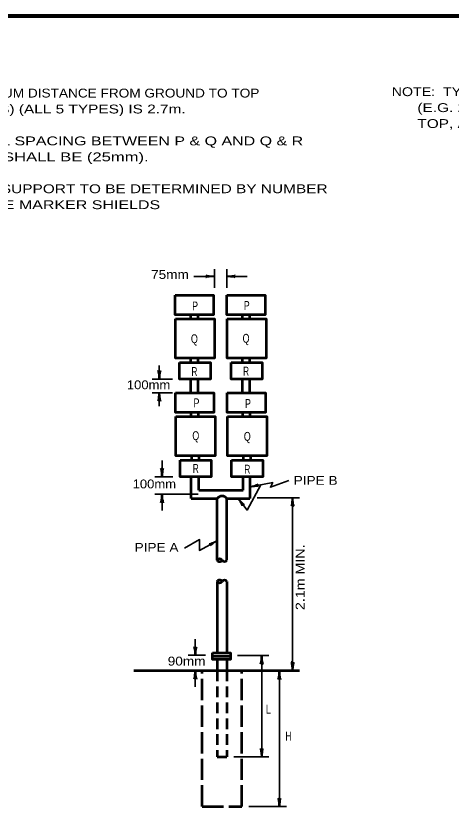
# Model space of a CAD drawing. Extents: x 11 to 867, y -284 to 260.
# Drawn here: x 281.9 to 429.3, y -14.9 to 254 of the extents above; entities that cross this region are included whole.
import ezdxf
from ezdxf.enums import TextEntityAlignment as Align

# ---------------------------------------------------------------- set-up
doc = ezdxf.new("R2010")
doc.units = 0
doc.header["$LTSCALE"] = 1.2
doc.linetypes.add('LONG_DASHED', pattern=[7.5, 6, -1.5])
doc.linetypes.add('MEDIUM_DASHED', pattern=[4.5, 3, -1.5])
doc.layers.add('1', color=7, linetype='Continuous', lineweight=53)

msp = doc.modelspace()

# ---------------------------------------------------------------- linework, layer by layer
at = {"layer": '1', "lineweight": 35}
for p, q in [((349.125, 161.883), (349.125, 168.204)), ((353.297, 161.883), (353.297, 168.204)), ((342.141, 165.805), (349.125, 165.805)), ((353.297, 165.805), (360.281, 165.805)), ((330.459, 131.031), (330.459, 135.62)), ((334.909, 131.031), (328.059, 131.031)), ((334.909, 126.419), (328.059, 126.419)), ((330.459, 121.829), (330.459, 126.419)), ((331.389, 97.999), (331.389, 103.499)), ((335.079, 97.967), (328.989, 97.967)), ((343.675, 92.038), (328.989, 92.038)), ((331.389, 86.538), (331.389, 92.038)), ((363.611, 90.861), (378.009, 90.861)), ((375.609, 32.333), (375.609, 90.861)), ((342.661, 37.489), (342.661, 43.001)), ((346.089, 37.489), (340.261, 37.489)), ((356.943, 37.381), (367.573, 37.381)), ((365.173, 37.381), (365.173, 3.099)), ((342.661, 26.821), (342.661, 32.333)), ((371.141, 32.206), (371.141, -13.726)), ((355.747, 3.099), (367.573, 3.099)), ((360.777, -13.726), (373.541, -13.726))]:
    msp.add_line(p, q, dxfattribs=at)
at = {"layer": '1'}
for p, q in [((341.177, 151.463), (341.177, 152.749)), ((343.685, 151.463), (343.685, 152.749)), ((358.679, 151.463), (358.679, 152.749)), ((361.187, 151.463), (361.187, 152.749)), ((341.177, 136.631), (341.177, 138.069)), ((343.685, 136.631), (343.685, 138.069)), ((358.679, 136.631), (358.679, 138.069)), ((361.187, 136.631), (361.187, 138.069)), ((341.177, 126.419), (341.177, 131.031)), ((343.685, 126.419), (343.685, 131.031)), ((358.679, 126.419), (358.679, 131.031)), ((361.187, 126.419), (361.187, 131.031)), ((341.177, 119.684), (341.177, 118.399)), ((343.685, 119.684), (343.685, 118.399)), ((358.679, 119.684), (358.679, 118.399)), ((361.187, 119.684), (361.187, 118.399)), ((341.413, 105.005), (341.413, 103.567)), ((343.857, 105.005), (343.857, 103.567)), ((358.915, 105.005), (358.915, 103.567)), ((361.359, 105.005), (361.359, 103.567)), ((341.275, 90.611), (341.275, 97.967)), ((343.879, 93.355), (343.879, 97.967)), ((358.849, 93.355), (358.849, 97.967)), ((361.211, 90.611), (361.211, 97.967)), ((343.879, 93.355), (358.849, 93.355)), ((341.275, 90.611), (350.073, 90.611)), ((350.073, 69.707), (350.073, 90.611)), ((353.347, 69.707), (353.347, 90.611)), ((353.347, 90.611), (361.185, 90.611)), ((350.075, 62.471), (350.075, 38.358)), ((353.347, 62.471), (353.347, 38.358)), ((348.489, 37.241), (354.543, 37.241)), ((350.075, 36.12), (350.075, 32.333)), ((353.347, 36.12), (353.347, 32.333)), ((321.829, 32.333), (378.009, 32.333))]:
    msp.add_line(p, q, dxfattribs=at)
at = {"layer": '1', "linetype": 'LONG_DASHED'}
msp.add_line((345.013, -13.726), (345.013, 32.333), dxfattribs=at)
at = {"layer": '1', "linetype": 'MEDIUM_DASHED'}
for p, q in [((350.075, 32.333), (350.075, 3.099)), ((353.347, 32.333), (353.347, 3.099)), ((350.075, 3.099), (353.347, 3.099))]:
    msp.add_line(p, q, dxfattribs=at)
at = {"layer": '1', "lineweight": 158}
msp.add_lwpolyline([(860.008, 254), (68.308, 253.9), (68.408, -272.101)], dxfattribs=at)
at = {"layer": '1'}
for points in [[(335.795, 159.483), (348.807, 159.483), (348.807, 152.749), (335.795, 152.749)], [(353.297, 159.483), (366.309, 159.483), (366.309, 152.749), (353.297, 152.749)], [(335.949, 151.463), (349.187, 151.463), (349.187, 138.069), (335.949, 138.069)], [(353.451, 151.463), (366.689, 151.463), (366.689, 138.069), (353.451, 138.069)], [(337.309, 136.631), (347.825, 136.631), (347.825, 131.031), (337.309, 131.031)], [(354.811, 136.631), (365.327, 136.631), (365.327, 131.031), (354.811, 131.031)], [(335.965, 126.419), (348.977, 126.419), (348.977, 119.684), (335.965, 119.684)], [(353.467, 126.419), (366.479, 126.419), (366.479, 119.684), (353.467, 119.684)], [(336.119, 118.399), (349.357, 118.399), (349.357, 105.005), (336.119, 105.005)], [(353.621, 118.399), (366.859, 118.399), (366.859, 105.005), (353.621, 105.005)], [(337.479, 103.567), (347.995, 103.567), (347.995, 97.967), (337.479, 97.967)], [(354.981, 103.567), (365.497, 103.567), (365.497, 97.967), (354.981, 97.967)], [(348.489, 38.358), (354.543, 38.358), (354.543, 36.12), (348.489, 36.12)]]:
    msp.add_lwpolyline(points, close=True, dxfattribs=at)
at = {"layer": '1', "lineweight": 35}
for points in [[(364.831, 95.209), (360.199, 86.669), (357.193, 90.611)], [(361.211, 94.532), (368.907, 95.969), (368.121, 94.397), (374.407, 96.689)], [(350.073, 76.264), (344.043, 73.031), (344.113, 76.654), (338.957, 73.727)]]:
    msp.add_lwpolyline(points, dxfattribs=at)
at = {"layer": '1', "linetype": 'LONG_DASHED'}
msp.add_lwpolyline([(345.013, -13.726), (358.377, -13.726), (358.377, 32.333)], dxfattribs=at)
at = {"layer": '1'}
for centre, radius, start, end in [((351.71, 89.228), 2.143, 40.17606, 139.82394), ((350.893, 69.15), 0.989, 34.21419, 145.78581), ((350.893, 70.145), 0.928, 208.21086, 331.78914), ((352.529, 70.286), 1.003, 215.33373, 324.66627), ((350.893, 62.032), 0.928, 28.21086, 151.78914), ((350.893, 63.027), 0.989, 214.21419, 325.78581), ((352.529, 61.891), 1.003, 35.33373, 144.66627)]:
    msp.add_arc(centre, radius, start, end, dxfattribs=at)
at = {"layer": '1', "lineweight": 40}
for centre, major_axis, ratio, start_param, end_param in [((348.034, 165.528), (1.786, 0.156), 0.122415, 0.8963533, 3.1415927), ((348.004, 166.016), (1.756, -0.176), 0.07063, 3.1407148, 5.41811), ((354.417, 165.593), (-1.756, 0.176), 0.07063, 3.1407148, 5.41811), ((354.417, 165.593), (-1.756, 0.176), 0.07063, 3.1407148, 5.41811), ((354.388, 166.081), (-1.786, -0.156), 0.122415, 0.8963533, 3.1415927), ((354.388, 166.081), (-1.786, -0.156), 0.122415, 0.8963533, 3.1415927), ((330.183, 132.122), (0.156, -1.786), 0.122415, 0.8963533, 3.1415927), ((330.67, 132.151), (-0.176, -1.756), 0.07063, 3.1407148, 5.41811), ((330.247, 125.298), (0.176, 1.756), 0.07063, 3.1407148, 5.41811), ((330.735, 125.327), (-0.156, 1.786), 0.122415, 0.8963533, 3.1415927), ((331.113, 99.09), (0.156, -1.786), 0.122415, 0.8963533, 3.1415927), ((331.113, 99.09), (0.156, -1.786), 0.122415, 0.8963533, 3.1415927), ((331.6, 99.119), (-0.176, -1.756), 0.07063, 3.1407148, 5.41811), ((331.6, 99.119), (-0.176, -1.756), 0.07063, 3.1407148, 5.41811), ((362.233, 95.004), (-1.727, -0.481), 0.122415, 0.8963533, 3.1415927), ((362.233, 95.004), (-1.727, -0.481), 0.122415, 0.8963533, 3.1415927), ((362.351, 94.53), (-1.759, -0.15), 0.07063, 3.1407148, 5.41811), ((362.351, 94.53), (-1.759, -0.15), 0.07063, 3.1407148, 5.41811), ((331.177, 90.918), (0.176, 1.756), 0.07063, 3.1407148, 5.41811), ((331.665, 90.947), (-0.156, 1.786), 0.122415, 0.8963533, 3.1415927), ((357.704, 89.591), (-0.925, 1.503), 0.07063, 3.1407148, 5.41811), ((358.074, 89.91), (-1.207, 1.325), 0.122415, 0.8963533, 3.1415927), ((375.397, 89.74), (0.176, 1.756), 0.07063, 3.1407148, 5.41811), ((375.885, 89.769), (-0.156, 1.786), 0.122415, 0.8963533, 3.1415927), ((348.985, 75.921), (1.631, 0.675), 0.07063, 3.1407148, 5.41811), ((349.242, 75.505), (1.5, 0.982), 0.122415, 0.8963533, 3.1415927), ((342.385, 38.58), (0.156, -1.786), 0.122415, 0.8963533, 3.1415927), ((342.385, 38.58), (0.156, -1.786), 0.122415, 0.8963533, 3.1415927), ((342.872, 38.609), (-0.176, -1.756), 0.07063, 3.1407148, 5.41811), ((342.872, 38.609), (-0.176, -1.756), 0.07063, 3.1407148, 5.41811), ((364.961, 36.26), (0.176, 1.756), 0.07063, 3.1407148, 5.41811), ((365.449, 36.289), (-0.156, 1.786), 0.122415, 0.8963533, 3.1415927), ((375.333, 33.424), (0.156, -1.786), 0.122415, 0.8963533, 3.1415927), ((375.82, 33.453), (-0.176, -1.756), 0.07063, 3.1407148, 5.41811), ((342.449, 31.212), (0.176, 1.756), 0.07063, 3.1407148, 5.41811), ((342.937, 31.241), (-0.156, 1.786), 0.122415, 0.8963533, 3.1415927), ((370.929, 31.086), (0.176, 1.756), 0.07063, 3.1407148, 5.41811), ((371.417, 31.115), (-0.156, 1.786), 0.122415, 0.8963533, 3.1415927), ((364.897, 4.19), (0.156, -1.786), 0.122415, 0.8963533, 3.1415927), ((365.384, 4.219), (-0.176, -1.756), 0.07063, 3.1407148, 5.41811), ((370.865, -12.634), (0.156, -1.786), 0.122415, 0.8963533, 3.1415927), ((371.352, -12.605), (-0.176, -1.756), 0.07063, 3.1407148, 5.41811)]:
    msp.add_ellipse(centre, major_axis=major_axis, ratio=ratio, start_param=start_param, end_param=end_param, dxfattribs=at)

# ---------------------------------------------------------------- texts
at = {"layer": '1'}
for s, width, p in [('NOTES:   MINIMUM DISTANCE FROM GROUND TO TOP', 1.15, (242.888, 226.364)), ('NOTE:  TYPE 4 SUPPORT TO HAVE CROSS-ARM', 1.2, (409.209, 226.831)), ('       OF SIGN(S) (ALL 5 TYPES) IS 2.7m.', 1.3, (242.888, 220.964)), ('      (E.G. 2.98kG/m U-CHANNEL, TELESPAR) AT', 1.3, (409.209, 221.431)), ('      TOP, AND BOTTOM AS APPROPRIATE.', 1.3, (409.209, 216.031)), ('       VERTICAL SPACING BETWEEN P & Q AND Q & R', 1.35, (242.888, 210.164)), ('       PANELS SHALL BE (25mm).', 1.4, (242.888, 204.764)), ('       TYPE OF SUPPORT TO BE DETERMINED BY NUMBER', 1.3, (242.888, 193.964)), ('       OF ROUTE MARKER SHIELDS', 1.35, (242.888, 188.564))]:
    msp.add_text(s, height=3, dxfattribs=dict(at, width=width)).set_placement(p)
for s, width, p in [('75mm', 1.15, (334.087, 164.927)), ('P', 0.75, (342.59, 154.281)), ('P', 0.75, (360.091, 154.431)), ('Q', 0.75, (342.353, 143.171)), ('Q', 0.75, (359.855, 143.322)), ('R', 0.7, (342.353, 132.062)), ('R', 0.7, (359.855, 132.213)), ('100mm', 1.1, (326.829, 127.585)), ('P', 0.75, (343.065, 121.471)), ('P', 0.75, (360.521, 121.233)), ('Q', 0.75, (342.829, 110.361)), ('Q', 0.75, (360.285, 110.124)), ('R', 0.7, (342.829, 99.252)), ('R', 0.7, (360.285, 99.014)), ('100mm', 1.1, (328.782, 94.018)), ('PIPE B', 1.15, (383.426, 95.214)), ('PIPE A', 1.15, (329.525, 72.538)), ('90mm', 1.15, (339.722, 34.028)), ('L', 0.75, (367.432, 17.731)), ('H', 0.7, (374.225, 8.629))]:
    msp.add_text(s, height=3, dxfattribs=dict(at, width=width)).set_placement(p, align=Align.CENTER)
at = {"layer": '1', "width": 1.2}
msp.add_text('2.1m MIN.', height=3, rotation=90, dxfattribs=at).set_placement((379.674, 63.915), align=Align.CENTER)

doc.saveas('drawing.dxf')
